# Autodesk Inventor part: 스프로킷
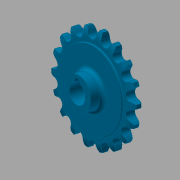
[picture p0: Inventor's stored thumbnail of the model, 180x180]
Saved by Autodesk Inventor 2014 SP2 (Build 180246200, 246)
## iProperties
Created: 2016-03
Part Number: 스프로킷
Material: 강철, 탄소
Document SubType Name: Modeling
Designer: mduedu
Density: 7.87 g/cm^3
Mass: 301.818 g
Surface Area: 124.882 cm^2
Volume: 38.3505 cm^3
Appearance: 하늘색 중간
Author: mduedu
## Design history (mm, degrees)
sketch "스케치1"
  geometry: L1 (0, 5)-(29.5, 5); L2 (29.5, 5)-(29.5, 4.1); L3 (30, 3.6)-(33.625, 3.6); L4 (40, 2)-(40, 0); L5 (40, 0)-(0, 0); L6 (0, 0)-(0, 5); L7 (0, -5)-(29.5, -5); L8 (29.5, -5)-(29.5, -4.1); L9 (30, -3.6)-(33.625, -3.6); L10 (40, -2)-(40, 0); L11 (0, 0)-(0, -5); A1 r 13.5 centre (33.625, -9.9) between (40, 2) and (33.625, 3.6); A2 r 13.5 centre (33.625, 9.9) between (33.625, -3.6) and (40, -2); A3 r 0.5 centre (30, 4.1) between (29.5, 4.1) and (30, 3.6); A4 r 0.5 centre (30, -4.1) between (30, -3.6) and (29.5, -4.1); 2 further points
  constraints: 22 end point, 8 point on circle, 6 symmetric about line, 5 tangent, 4 centre point, 4 parallel, 4 point on line, 1 equal radius, 1 horizontal, 1 perpendicular, 1 other
  dimensions: "d0" = 80 diameter of L4 L6; "d2" = 59 diameter of L2 L6; "d3" = 1.6 vertical distance of L4.start L3.end; "d4" = 3.6 distance from line of L4.end L3; "d5" = 5 distance between parallel lines of L5 L1; "d6" = 13.5 radius of A1; "d15" = 0.5 radius of A3
revolve "회전1" sketch "스케치1" stored, may be unused: angle "d7" = 90 deg
sketch "스케치2" dims "d8" = 65.2, "d11" = 80
  geometry: L1 (0, 0)-(0, 32.6); A1 r 36.57 centre (0, 0) between (-16.231, 32.771) and (0, 36.57); A2 r 3.97 centre (0, 36.57) between (-3.866, 35.665) and (0, 32.6); A3 r 12.7 centre (-16.231, 32.771) between (-3.866, 35.665) and (-5.534, 39.615); A4 r 12.7 centre (16.231, 32.771) between (5.534, 39.615) and (3.866, 35.665); A5 r 3.97 centre (0, 36.57) between (0, 32.6) and (3.866, 35.665); A6 r 40 centre (0, 0) between (5.534, 39.615) and (-5.534, 39.615); 2 further points
  constraints: 12 point on circle, 6 centre point, 4 coincident, 3 symmetric about line, 2 end point, 1 point on line, 1 tangent, 1 vertical, 1 vertical alignment, 7 other
  dimensions: "d10" = 73.14 diameter of A1; "d12" = 12.7 radius of A3
extrude "돌출1" cut sketch "스케치2" stored distance "d13" = 10; taper "d14" = 0 deg
sketch "스케치3"
  geometry: C1 r 12.5 at (0, 0); 1 further point
  constraints: 1 centre point, 1 coincident
  dimensions: "d19" = 25 diameter of C1
extrude "돌출2" join sketch "스케치3" distance "d20" = 10; taper "d21" = 0 deg
fillet "모깎기1" dims "d22" = 3
sketch "스케치4"
  geometry: L1 (-2.5, 0)-(2.5, 0); L2 (2.5, 0)-(2.5, 9.8); L3 (2.5, 9.8)-(-2.5, 9.8); L4 (-2.5, 9.8)-(-2.5, 0); C1 r 7.5 at (0, 0); 2 further points
  constraints: 8 end point, 2 coincident, 2 parallel, 1 centre point, 1 horizontal, 1 midpoint, 1 perpendicular
  dimensions: "d23" = 15 diameter of C1; "d25" = 5 distance of L2.end L3.end; "d26" = 9.8 distance of L1.end L2.end
extrude "돌출3" cut sketch "스케치4" stored distance "d27" = 8; taper "d28" = 0 deg
node "솔리드1"
pattern_circular "원형 패턴1" dims angle "d17" = 360 deg
